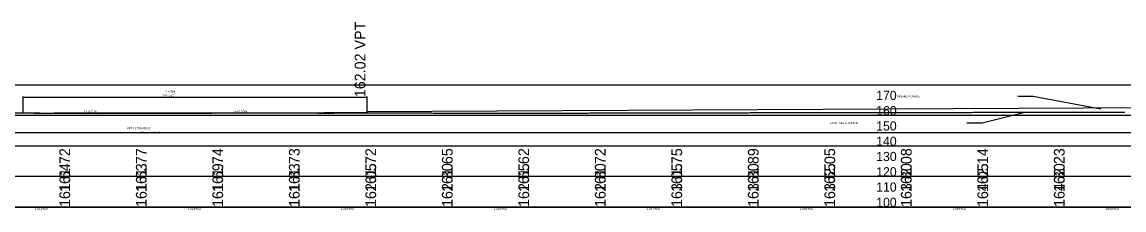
# Model space of a CAD drawing. Extents: x 2126510 to 2136144, y 865066 to 868066.
# Drawn here: x 2127736 to 2128457, y 866612 to 866735 of the extents above; entities that cross this region are included whole.
import ezdxf

# ---------------------------------------------------------------- set-up
doc = ezdxf.new("R2010")
doc.units = 0
for name, color, linetype in [('RD_EX_GuardRail', 7, 'Continuous'), ('RD_EX_H2O', 7, 'Continuous'), ('RD_EX_Misc', 7, 'Continuous')]:
    doc.layers.add(name, color=color, linetype=linetype)

msp = doc.modelspace()

# ---------------------------------------------------------------- linework, layer by layer
at = {"layer": 'RD_EX_GuardRail'}
for p, q in [((2131097.7, 866693.9), (2126517.45, 866693.9)), ((2128999.96, 866673.9), (2126517.45, 866673.9)), ((2131097.7, 866653.9), (2126517.45, 866653.9)), ((2131097.7, 866633.9), (2126517.45, 866633.9)), ((2131097.7, 866613.9), (2126517.45, 866613.9))]:
    msp.add_line(p, q, dxfattribs=at)
at = {"layer": 'RD_EX_H2O'}
for points in [[(2127736.19, 866675.58), (2127737.19, 866675.58)], [(2127937.19, 866675.57), (2127938.19, 866675.57), (2127939.19, 866675.57), (2127940.19, 866675.57), (2127941.19, 866675.58), (2127942.19, 866675.58), (2127943.19, 866675.58), (2127944.19, 866675.58), (2127945.19, 866675.58), (2127946.19, 866675.58), (2127947.19, 866675.58), (2127948.19, 866675.59), (2127949.19, 866675.59), (2127950.19, 866675.59), (2127951.19, 866675.59), (2127952.19, 866675.59), (2127953.19, 866675.59), (2127954.19, 866675.6), (2127955.19, 866675.6), (2127956.19, 866675.6), (2127957.19, 866675.6), (2127958.19, 866675.6), (2127959.19, 866675.6), (2127960.19, 866675.61), (2127961.19, 866675.61), (2127962.19, 866675.61), (2127963.19, 866675.61), (2127964.19, 866675.61), (2127965.19, 866675.62), (2127966.19, 866675.62), (2127967.19, 866675.62), (2127968.19, 866675.62), (2127969.19, 866675.62), (2127970.19, 866675.63), (2127971.19, 866675.63), (2127972.19, 866675.63), (2127973.19, 866675.63), (2127974.19, 866675.63), (2127975.19, 866675.63), (2127976.19, 866675.63), (2127977.19, 866675.63), (2127978.19, 866675.63), (2127979.19, 866675.63), (2127980.19, 866675.63), (2127981.19, 866675.62), (2127982.19, 866675.62), (2127983.19, 866675.62), (2127984.19, 866675.62), (2127985.19, 866675.62), (2127986.19, 866675.62), (2127987.19, 866675.62), (2127988.19, 866675.62), (2127989.19, 866675.62), (2127990.19, 866675.61), (2127991.19, 866675.61), (2127992.19, 866675.61), (2127993.19, 866675.61), (2127994.19, 866675.61), (2127995.19, 866675.6), (2127996.19, 866675.6), (2127997.19, 866675.6), (2127998.19, 866675.59), (2127999.19, 866675.59), (2128000.19, 866675.59), (2128001.19, 866675.59), (2128002.19, 866675.58), (2128003.19, 866675.58), (2128004.19, 866675.58), (2128005.19, 866675.57), (2128006.19, 866675.57), (2128007.19, 866675.57), (2128008.19, 866675.57), (2128009.19, 866675.56), (2128010.19, 866675.56), (2128011.19, 866675.56), (2128012.19, 866675.55), (2128013.19, 866675.55), (2128014.19, 866675.55), (2128015.19, 866675.55), (2128016.19, 866675.55), (2128017.19, 866675.55), (2128018.19, 866675.55), (2128019.19, 866675.56), (2128020.19, 866675.56), (2128021.19, 866675.56), (2128022.19, 866675.56), (2128023.19, 866675.56), (2128024.19, 866675.56), (2128025.19, 866675.56), (2128026.19, 866675.56), (2128027.19, 866675.56), (2128028.19, 866675.57), (2128029.19, 866675.57), (2128030.19, 866675.57), (2128031.19, 866675.57), (2128032.19, 866675.57), (2128033.19, 866675.57), (2128034.19, 866675.57), (2128035.19, 866675.57), (2128036.19, 866675.57), (2128037.19, 866675.57)], [(2128037.19, 866675.57), (2128038.19, 866675.57), (2128039.19, 866675.57), (2128040.19, 866675.56), (2128041.19, 866675.56), (2128042.19, 866675.56), (2128043.19, 866675.56), (2128044.19, 866675.56), (2128045.19, 866675.56), (2128046.19, 866675.56), (2128047.19, 866675.56), (2128048.19, 866675.55), (2128049.19, 866675.55), (2128050.19, 866675.55), (2128051.19, 866675.55), (2128052.19, 866675.55), (2128053.19, 866675.55), (2128054.19, 866675.55), (2128055.19, 866675.54), (2128056.19, 866675.54), (2128057.19, 866675.54), (2128058.19, 866675.54), (2128059.19, 866675.54), (2128060.19, 866675.54), (2128061.19, 866675.54), (2128062.19, 866675.53), (2128063.19, 866675.53), (2128064.19, 866675.53), (2128065.19, 866675.53), (2128066.19, 866675.52), (2128067.19, 866675.52), (2128068.19, 866675.52), (2128069.19, 866675.52), (2128070.19, 866675.52), (2128071.19, 866675.52), (2128072.19, 866675.52), (2128073.19, 866675.52), (2128074.19, 866675.52), (2128075.19, 866675.52), (2128076.19, 866675.52), (2128077.19, 866675.52), (2128078.19, 866675.52), (2128079.19, 866675.51), (2128080.19, 866675.51), (2128081.19, 866675.51), (2128082.19, 866675.51), (2128083.19, 866675.51), (2128084.19, 866675.51), (2128085.19, 866675.51), (2128086.19, 866675.5), (2128087.19, 866675.5), (2128088.19, 866675.5), (2128089.19, 866675.5), (2128090.19, 866675.5), (2128091.19, 866675.5), (2128092.19, 866675.5), (2128093.19, 866675.51), (2128094.19, 866675.51), (2128095.19, 866675.52), (2128096.19, 866675.52), (2128097.19, 866675.53), (2128098.19, 866675.53), (2128099.19, 866675.54), (2128100.19, 866675.54), (2128101.19, 866675.55), (2128102.19, 866675.55), (2128103.19, 866675.56), (2128104.19, 866675.56), (2128105.19, 866675.57), (2128106.19, 866675.57), (2128107.19, 866675.58), (2128108.19, 866675.58), (2128109.19, 866675.59), (2128110.19, 866675.6), (2128111.19, 866675.61), (2128112.19, 866675.61), (2128113.19, 866675.61), (2128114.19, 866675.61), (2128115.19, 866675.61), (2128116.19, 866675.62), (2128117.19, 866675.62), (2128118.19, 866675.62), (2128119.19, 866675.62), (2128120.19, 866675.62), (2128121.19, 866675.62), (2128122.19, 866675.63), (2128123.19, 866675.63), (2128124.19, 866675.63), (2128125.19, 866675.63), (2128126.19, 866675.63), (2128127.19, 866675.64), (2128128.19, 866675.64), (2128129.19, 866675.64), (2128130.19, 866675.64), (2128131.19, 866675.64), (2128132.19, 866675.64), (2128133.19, 866675.63), (2128134.19, 866675.63), (2128135.19, 866675.64), (2128136.19, 866675.64), (2128137.19, 866675.65)], [(2128137.19, 866675.65), (2128138.19, 866675.66), (2128139.19, 866675.66), (2128140.19, 866675.67), (2128141.19, 866675.67), (2128142.19, 866675.68), (2128143.19, 866675.69), (2128144.19, 866675.69), (2128145.19, 866675.7), (2128146.19, 866675.7), (2128147.19, 866675.71), (2128148.19, 866675.72), (2128149.19, 866675.72), (2128150.19, 866675.72), (2128151.19, 866675.72), (2128152.19, 866675.72), (2128153.19, 866675.72), (2128154.19, 866675.72), (2128155.19, 866675.71), (2128156.19, 866675.71), (2128157.19, 866675.7), (2128158.19, 866675.7), (2128159.19, 866675.69), (2128160.19, 866675.68), (2128161.19, 866675.68), (2128162.19, 866675.67), (2128163.19, 866675.67), (2128164.19, 866675.66), (2128165.19, 866675.66), (2128166.19, 866675.65), (2128167.19, 866675.65), (2128168.19, 866675.65), (2128169.19, 866675.66), (2128170.19, 866675.66), (2128171.19, 866675.67), (2128172.19, 866675.68), (2128173.19, 866675.68), (2128174.19, 866675.68), (2128175.19, 866675.69), (2128176.19, 866675.69), (2128177.19, 866675.69), (2128178.19, 866675.69), (2128179.19, 866675.7), (2128180.19, 866675.7), (2128181.19, 866675.7), (2128182.19, 866675.7), (2128183.19, 866675.71), (2128184.19, 866675.71), (2128185.19, 866675.71), (2128186.19, 866675.71), (2128187.19, 866675.72), (2128188.19, 866675.72), (2128189.19, 866675.72), (2128190.19, 866675.71), (2128191.19, 866675.71), (2128192.19, 866675.7), (2128193.19, 866675.7), (2128194.19, 866675.69), (2128195.19, 866675.69), (2128196.19, 866675.7), (2128197.19, 866675.71), (2128198.19, 866675.71), (2128199.19, 866675.72), (2128200.19, 866675.72), (2128201.19, 866675.73), (2128202.19, 866675.74), (2128203.19, 866675.74), (2128204.19, 866675.75), (2128205.19, 866675.76), (2128206.19, 866675.76), (2128207.19, 866675.77), (2128208.19, 866675.78), (2128209.19, 866675.78), (2128210.19, 866675.79), (2128211.19, 866675.79), (2128212.19, 866675.8), (2128213.19, 866675.8), (2128214.19, 866675.8), (2128215.19, 866675.8), (2128216.19, 866675.8), (2128217.19, 866675.8), (2128218.19, 866675.8), (2128219.19, 866675.8), (2128220.19, 866675.8), (2128221.19, 866675.8), (2128222.19, 866675.8), (2128223.19, 866675.8), (2128224.19, 866675.8), (2128225.19, 866675.8), (2128226.19, 866675.8), (2128227.19, 866675.8), (2128228.19, 866675.8), (2128229.19, 866675.8), (2128230.19, 866675.8), (2128231.19, 866675.8), (2128232.19, 866675.8), (2128233.19, 866675.8), (2128234.19, 866675.8), (2128235.19, 866675.8), (2128236.19, 866675.8), (2128237.19, 866675.8)], [(2128237.19, 866675.8), (2128238.19, 866675.8), (2128239.19, 866675.8), (2128240.19, 866675.8), (2128241.19, 866675.8), (2128242.19, 866675.8), (2128243.19, 866675.8), (2128244.19, 866675.8), (2128245.19, 866675.8), (2128246.19, 866675.81), (2128247.19, 866675.82), (2128248.19, 866675.83), (2128249.19, 866675.83), (2128250.19, 866675.84), (2128251.19, 866675.85), (2128252.19, 866675.86), (2128253.19, 866675.86), (2128254.19, 866675.87), (2128255.19, 866675.87), (2128256.19, 866675.88), (2128257.19, 866675.89), (2128258.19, 866675.89), (2128259.19, 866675.9), (2128260.19, 866675.91), (2128261.19, 866675.91), (2128262.19, 866675.92), (2128263.19, 866675.93), (2128264.19, 866675.93), (2128265.19, 866675.94), (2128266.19, 866675.95), (2128267.19, 866675.95), (2128268.19, 866675.95), (2128269.19, 866675.95), (2128270.19, 866675.95), (2128271.19, 866675.95), (2128272.19, 866675.95), (2128273.19, 866675.95), (2128274.19, 866675.95), (2128275.19, 866675.95), (2128276.19, 866675.95), (2128277.19, 866675.94), (2128278.19, 866675.94), (2128279.19, 866675.94), (2128280.19, 866675.94), (2128281.19, 866675.94), (2128282.19, 866675.94), (2128283.19, 866675.93), (2128284.19, 866675.93), (2128285.19, 866675.93), (2128286.19, 866675.93), (2128287.19, 866675.93), (2128288.19, 866675.92), (2128289.19, 866675.92), (2128290.19, 866675.92), (2128291.19, 866675.93), (2128292.19, 866675.93), (2128293.19, 866675.93), (2128294.19, 866675.93), (2128295.19, 866675.94), (2128296.19, 866675.94), (2128297.19, 866675.94), (2128298.19, 866675.94), (2128299.19, 866675.95), (2128300.19, 866675.95), (2128301.19, 866675.95), (2128302.19, 866675.95), (2128303.19, 866675.96), (2128304.19, 866675.96), (2128305.19, 866675.96), (2128306.19, 866675.97), (2128307.19, 866675.97), (2128308.19, 866675.97), (2128309.19, 866675.98), (2128310.19, 866675.98), (2128311.19, 866675.98), (2128312.19, 866675.98), (2128313.19, 866675.98), (2128314.19, 866675.98), (2128315.19, 866675.98), (2128316.19, 866675.98), (2128317.19, 866675.98), (2128318.19, 866675.98), (2128319.19, 866675.98), (2128320.19, 866675.98), (2128321.19, 866675.98), (2128322.19, 866675.98), (2128323.19, 866675.97), (2128324.19, 866675.97), (2128325.19, 866675.97), (2128326.19, 866675.97), (2128327.19, 866675.96), (2128328.19, 866675.96), (2128329.19, 866675.96), (2128330.19, 866675.96), (2128331.19, 866675.96), (2128332.19, 866675.96), (2128333.19, 866675.96), (2128334.19, 866675.96), (2128335.19, 866675.97), (2128336.19, 866675.97), (2128337.19, 866675.97)], [(2128337.19, 866675.97), (2128338.19, 866675.97), (2128339.19, 866675.98), (2128340.19, 866675.98), (2128341.19, 866675.98), (2128342.19, 866675.98), (2128343.19, 866675.99), (2128344.19, 866675.99), (2128345.19, 866675.99), (2128346.19, 866675.99), (2128347.19, 866675.99), (2128348.19, 866676), (2128349.19, 866676), (2128350.19, 866676), (2128351.19, 866676), (2128352.19, 866676), (2128353.19, 866676.01), (2128354.19, 866676.01), (2128355.19, 866676.01), (2128356.19, 866676.01), (2128357.19, 866676.01), (2128358.19, 866676.02), (2128359.19, 866676.02), (2128360.19, 866676.02), (2128361.19, 866676.02), (2128362.19, 866676.02), (2128363.19, 866676.03), (2128364.19, 866676.03), (2128365.19, 866676.03), (2128366.19, 866676.03), (2128367.19, 866676.03), (2128368.19, 866676.04), (2128369.19, 866676.04), (2128370.19, 866676.04), (2128371.19, 866676.05), (2128372.19, 866676.05), (2128373.19, 866676.05), (2128374.19, 866676.06), (2128375.19, 866676.06), (2128376.19, 866676.06), (2128377.19, 866676.07), (2128378.19, 866676.07), (2128379.19, 866676.08), (2128380.19, 866676.08), (2128381.19, 866676.09), (2128382.19, 866676.09), (2128383.19, 866676.1), (2128384.19, 866676.11), (2128385.19, 866676.11), (2128386.19, 866676.12), (2128387.19, 866676.12), (2128388.19, 866676.13), (2128389.19, 866676.12), (2128390.19, 866676.12), (2128391.19, 866676.12), (2128392.19, 866676.11), (2128393.19, 866676.11), (2128394.19, 866676.1), (2128395.19, 866676.1), (2128396.19, 866676.1), (2128397.19, 866676.09), (2128398.19, 866676.09), (2128399.19, 866676.09), (2128400.19, 866676.09), (2128401.19, 866676.09), (2128402.19, 866676.09), (2128403.19, 866676.09), (2128404.19, 866676.09), (2128405.19, 866676.1), (2128406.19, 866676.1), (2128407.19, 866676.1), (2128408.19, 866676.1), (2128409.19, 866676.1), (2128410.19, 866676.11), (2128411.19, 866676.11), (2128412.19, 866676.11), (2128413.19, 866676.12), (2128414.19, 866676.12), (2128415.19, 866676.12), (2128416.19, 866676.13), (2128417.19, 866676.13), (2128418.19, 866676.13), (2128419.19, 866676.14), (2128420.19, 866676.14), (2128421.19, 866676.14), (2128422.19, 866676.15), (2128423.19, 866676.15), (2128424.19, 866676.14), (2128425.19, 866676.14), (2128426.19, 866676.14), (2128427.19, 866676.14), (2128428.19, 866676.14), (2128429.19, 866676.14), (2128430.19, 866676.13), (2128431.19, 866676.13), (2128432.19, 866676.13), (2128433.19, 866676.13), (2128434.19, 866676.13), (2128435.19, 866676.13), (2128436.19, 866676.13), (2128437.19, 866676.13)], [(2128437.19, 866676.13), (2128438.19, 866676.14), (2128439.19, 866676.14), (2128440.19, 866676.14), (2128441.19, 866676.14), (2128442.19, 866676.14), (2128443.19, 866676.14), (2128444.19, 866676.14), (2128445.19, 866676.14), (2128446.19, 866676.15), (2128447.19, 866676.16), (2128448.19, 866676.17), (2128449.19, 866676.18), (2128450.19, 866676.18), (2128451.19, 866676.19), (2128452.19, 866676.2), (2128453.19, 866676.21), (2128454.19, 866676.22), (2128455.19, 866676.22), (2128456.19, 866676.22), (2128457.19, 866676.22)]]:
    msp.add_lwpolyline(points, dxfattribs=at)
at = {"layer": 'RD_EX_Misc'}
for p, q in [((2127736.73, 866686.42), (2127736.73, 866675.59)), ((2127736.73, 866685.92), (2127961.73, 866685.92)), ((2127961.73, 866686.42), (2127961.73, 866675.92)), ((2127961.73, 866676.62), (2129142.37, 866682.52)), ((2127722.94, 866675.62), (2127736.73, 866675.59)), ((2127769.23, 866675.53), (2127849.23, 866675.36)), ((2127929.2, 866675.76), (2127849.23, 866675.36)), ((2127368.72, 866613.9), (2131522.97, 866613.9))]:
    msp.add_line(p, q, dxfattribs=at)
for points in [[(2128387.18, 866686.52), (2128397.11, 866686.52), (2128441.39, 866678.32)], [(2127737.19, 866675.58), (2127738.19, 866675.58), (2127739.19, 866675.58), (2127740.19, 866675.58), (2127741.19, 866675.58), (2127742.19, 866675.58), (2127743.19, 866675.58), (2127744.19, 866675.57), (2127745.19, 866675.57), (2127746.19, 866675.57), (2127747.19, 866675.57), (2127748.19, 866675.57), (2127749.19, 866675.57), (2127750.19, 866675.57), (2127751.19, 866675.57), (2127752.19, 866675.57), (2127753.19, 866675.57), (2127754.19, 866675.57), (2127755.19, 866675.57), (2127756.19, 866675.57), (2127757.19, 866675.58), (2127758.19, 866675.58), (2127759.19, 866675.59), (2127760.19, 866675.59), (2127761.19, 866675.59), (2127762.19, 866675.6), (2127763.19, 866675.6), (2127764.19, 866675.6), (2127765.19, 866675.61), (2127766.19, 866675.61), (2127767.19, 866675.61), (2127768.19, 866675.62), (2127769.19, 866675.62), (2127770.19, 866675.62), (2127771.19, 866675.63), (2127772.19, 866675.63), (2127773.19, 866675.64), (2127774.19, 866675.64), (2127775.19, 866675.64), (2127776.19, 866675.64), (2127777.19, 866675.64), (2127778.19, 866675.64), (2127779.19, 866675.64), (2127780.19, 866675.64), (2127781.19, 866675.64), (2127782.19, 866675.64), (2127783.19, 866675.65), (2127784.19, 866675.65), (2127785.19, 866675.65), (2127786.19, 866675.65), (2127787.19, 866675.65), (2127788.19, 866675.65), (2127789.19, 866675.65), (2127790.19, 866675.65), (2127791.19, 866675.65), (2127792.19, 866675.65), (2127793.19, 866675.66), (2127794.19, 866675.66), (2127795.19, 866675.66), (2127796.19, 866675.66), (2127797.19, 866675.66), (2127798.19, 866675.66), (2127799.19, 866675.66), (2127800.19, 866675.66), (2127801.19, 866675.66), (2127802.19, 866675.66), (2127803.19, 866675.66), (2127804.19, 866675.66), (2127805.19, 866675.66), (2127806.19, 866675.66), (2127807.19, 866675.66), (2127808.19, 866675.67), (2127809.19, 866675.67), (2127810.19, 866675.67), (2127811.19, 866675.67), (2127812.19, 866675.67), (2127813.19, 866675.67), (2127814.19, 866675.67), (2127815.19, 866675.67), (2127816.19, 866675.67), (2127817.19, 866675.67), (2127818.19, 866675.67), (2127819.19, 866675.67), (2127820.19, 866675.67), (2127821.19, 866675.67), (2127822.19, 866675.67), (2127823.19, 866675.67), (2127824.19, 866675.67), (2127825.19, 866675.67), (2127826.19, 866675.67), (2127827.19, 866675.67), (2127828.19, 866675.67), (2127829.19, 866675.67), (2127830.19, 866675.67), (2127831.19, 866675.67), (2127832.19, 866675.67), (2127833.19, 866675.67), (2127834.19, 866675.67), (2127835.19, 866675.67), (2127836.19, 866675.67), (2127837.19, 866675.66)], [(2127837.19, 866675.66), (2127838.19, 866675.66), (2127839.19, 866675.66), (2127840.19, 866675.66), (2127841.19, 866675.66), (2127842.19, 866675.65), (2127843.19, 866675.65), (2127844.19, 866675.65), (2127845.19, 866675.65), (2127846.19, 866675.65), (2127847.19, 866675.64), (2127848.19, 866675.64), (2127849.19, 866675.64), (2127850.19, 866675.64), (2127851.19, 866675.64), (2127852.19, 866675.64), (2127853.19, 866675.63), (2127854.19, 866675.63), (2127855.19, 866675.63), (2127856.19, 866675.63), (2127857.19, 866675.63), (2127858.19, 866675.63), (2127859.19, 866675.63), (2127860.19, 866675.64), (2127861.19, 866675.64), (2127862.19, 866675.64), (2127863.19, 866675.64), (2127864.19, 866675.64), (2127865.19, 866675.64), (2127866.19, 866675.64), (2127867.19, 866675.64), (2127868.19, 866675.64), (2127869.19, 866675.64), (2127870.19, 866675.64), (2127871.19, 866675.65), (2127872.19, 866675.65), (2127873.19, 866675.65), (2127874.19, 866675.65), (2127875.19, 866675.65), (2127876.19, 866675.65), (2127877.19, 866675.65), (2127878.19, 866675.65), (2127879.19, 866675.65), (2127880.19, 866675.65), (2127881.19, 866675.66), (2127882.19, 866675.66), (2127883.19, 866675.66), (2127884.19, 866675.66), (2127885.19, 866675.66), (2127886.19, 866675.66), (2127887.19, 866675.67), (2127888.19, 866675.67), (2127889.19, 866675.67), (2127890.19, 866675.67), (2127891.19, 866675.67), (2127892.19, 866675.67), (2127893.19, 866675.68), (2127894.19, 866675.68), (2127895.19, 866675.68), (2127896.19, 866675.68), (2127897.19, 866675.68), (2127898.19, 866675.68), (2127899.19, 866675.68), (2127900.19, 866675.67), (2127901.19, 866675.67), (2127902.19, 866675.67), (2127903.19, 866675.67), (2127904.19, 866675.67), (2127905.19, 866675.67), (2127906.19, 866675.67), (2127907.19, 866675.67), (2127908.19, 866675.66), (2127909.19, 866675.66), (2127910.19, 866675.66), (2127911.19, 866675.66), (2127912.19, 866675.66), (2127913.19, 866675.66), (2127914.19, 866675.65), (2127915.19, 866675.65), (2127916.19, 866675.64), (2127917.19, 866675.64), (2127918.19, 866675.63), (2127919.19, 866675.63), (2127920.19, 866675.62), (2127921.19, 866675.62), (2127922.19, 866675.61), (2127923.19, 866675.61), (2127924.19, 866675.6), (2127925.19, 866675.6), (2127926.19, 866675.59), (2127927.19, 866675.59), (2127928.19, 866675.58), (2127929.19, 866675.58), (2127930.19, 866675.57), (2127931.19, 866675.57), (2127932.19, 866675.56), (2127933.19, 866675.56), (2127934.19, 866675.57), (2127935.19, 866675.57), (2127936.19, 866675.57), (2127937.19, 866675.57)], [(2128353.72, 866669.04), (2128363.91, 866669.04), (2128391.69, 866676.11)], [(2127275.85, 866613.9), (2127275.85, 866662.9), (2131989.68, 866662.9)]]:
    msp.add_lwpolyline(points, dxfattribs=at)
msp.add_spline([(2127736.73, 866675.59), (2127741.23, 866675.58), (2127745.73, 866675.58), (2127750.23, 866675.57), (2127754.73, 866675.56), (2127759.23, 866675.56), (2127763.73, 866675.55), (2127768.23, 866675.54), (2127772.73, 866675.54), (2127777.23, 866675.54), (2127781.73, 866675.53), (2127786.23, 866675.53), (2127790.73, 866675.53), (2127795.23, 866675.53), (2127799.73, 866675.53), (2127804.23, 866675.52), (2127808.73, 866675.53), (2127813.23, 866675.53), (2127817.73, 866675.53), (2127822.23, 866675.53), (2127826.73, 866675.53), (2127831.23, 866675.54), (2127835.73, 866675.54), (2127840.23, 866675.55), (2127844.73, 866675.55), (2127849.23, 866675.56), (2127853.73, 866675.57), (2127858.23, 866675.57), (2127862.73, 866675.58), (2127867.23, 866675.59), (2127871.73, 866675.6), (2127876.23, 866675.61), (2127880.73, 866675.62), (2127885.23, 866675.63), (2127889.73, 866675.64), (2127894.23, 866675.66), (2127898.73, 866675.67), (2127903.23, 866675.68), (2127907.73, 866675.7), (2127912.23, 866675.71), (2127916.73, 866675.73), (2127921.23, 866675.75), (2127925.73, 866675.76), (2127930.23, 866675.78), (2127934.73, 866675.8), (2127939.23, 866675.82), (2127943.73, 866675.84), (2127948.23, 866675.86), (2127952.73, 866675.88), (2127957.23, 866675.9), (2127961.73, 866675.92)], degree=3, dxfattribs=at)

# ---------------------------------------------------------------- texts
for s, height, rotation, p in [('162.02 VPT', 7, 90, (2127960.73, 866685.92)), ('(-) 0.21%', 1.402, 359.88053, (2127776.93, 866675.91)), ('(+) 0.50%', 1.41, 0.28648, (2127874.84, 866675.89)), ('161.72', 7, 90, (2127767.72, 866623.9)), ('161.77', 7, 90, (2127817.72, 866623.9)), ('161.74', 7, 90, (2127867.72, 866623.9)), ('161.73', 7, 90, (2127917.72, 866623.9)), ('161.72', 7, 90, (2127967.72, 866623.9)), ('161.65', 7, 90, (2128017.72, 866623.9)), ('161.62', 7, 90, (2128067.72, 866623.9)), ('161.72', 7, 90, (2128117.72, 866623.9)), ('161.75', 7, 90, (2128167.72, 866623.9)), ('161.89', 7, 90, (2128217.72, 866623.9)), ('162.05', 7, 90, (2128267.72, 866623.9)), ('162.08', 7, 90, (2128317.72, 866623.9)), ('162.14', 7, 90, (2128367.72, 866623.9)), ('162.23', 7, 90, (2128417.72, 866623.9)), ('161.64', 7, 90, (2127767.72, 866614.05)), ('161.63', 7, 90, (2127817.72, 866614.05)), ('161.69', 7, 90, (2127867.72, 866614.05)), ('161.83', 7, 90, (2127917.72, 866614.05)), ('162.05', 7, 90, (2127967.72, 866614.05)), ('162.30', 7, 90, (2128017.72, 866614.05)), ('162.55', 7, 90, (2128067.72, 866614.05)), ('162.80', 7, 90, (2128117.72, 866614.05)), ('163.05', 7, 90, (2128167.72, 866614.05)), ('163.30', 7, 90, (2128217.72, 866614.05)), ('163.55', 7, 90, (2128267.72, 866614.05)), ('163.80', 7, 90, (2128317.72, 866614.05)), ('164.05', 7, 90, (2128367.72, 866614.05)), ('164.30', 7, 90, (2128417.72, 866614.05))]:
    msp.add_text(s, height=height, rotation=rotation, dxfattribs=at).set_placement(p)
for s, height, p in [("225' V.C.", 1.4, (2127827.97, 866686.17)), ('K = 318', 1.4, (2127829.67, 866688.97)), ('170', 6, (2128294.57, 866684.1)), ('FINISHED GRADE', 1.4, (2128306.71, 866685.82)), ('160', 6, (2128294.57, 866674.1)), ('VPI = 1793+80.51', 1.4, (2127804.75, 866664.96)), ('Elev. = 161.46', 1.4, (2127814.17, 866661.96)), ('EXISTING GROUND', 1.4, (2128264.41, 866668.34)), ('150', 6, (2128294.57, 866664.1)), ('140', 6, (2128294.57, 866654.1)), ('130', 6, (2128294.57, 866644.1)), ('120', 6, (2128294.57, 866634.1)), ('110', 6, (2128294.57, 866624.1)), ('100', 6, (2128294.57, 866614.1)), ('1793+00', 1.6, (2127744.51, 866612.1)), ('1794+00', 1.6, (2127844.51, 866612.1)), ('1795+00', 1.6, (2127944.51, 866612.1)), ('1796+00', 1.6, (2128044.51, 866612.1)), ('1797+00', 1.6, (2128144.51, 866612.1)), ('1798+00', 1.6, (2128244.51, 866612.1)), ('1799+00', 1.6, (2128344.51, 866612.1)), ('1800+00', 1.6, (2128444.51, 866612.1))]:
    msp.add_text(s, height=height, dxfattribs=at).set_placement(p)

doc.saveas('drawing.dxf')
